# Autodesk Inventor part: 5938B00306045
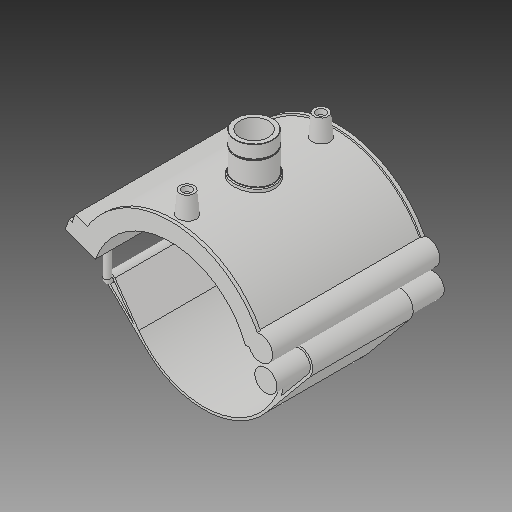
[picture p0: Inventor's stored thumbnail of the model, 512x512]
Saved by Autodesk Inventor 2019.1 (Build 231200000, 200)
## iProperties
Created: 2017-07
Part Number: 5938B00306045
Material: Generic
Description: PLASSON TRANSITION SADDLE 6''IPS x 1"NPT
Document SubType Name: Modeling
Designer: KIM
Density: 1 g/cm^3
Appearance: Default
Author: KIM
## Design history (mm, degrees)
derived "5938B.ipt"
feature "Solid1::5938B.ipt"
tag "TaggingFeature1"
body "Solid1"
other parameters: "d_" = 168, "B_" = 173.736, "H_" = 41.91, "L_" = 176.022, "d_t" = 6, "G_" = 30.291, "d148" = 2.52, "d160" = 2.52, "d169" = 2.52, "d192" = 6.72, "d0" = 168, "d1" = 201.6, "d2" = 434.34, "d3" = 42, "d4" = 176.022, "d5" = 0, "d40" = 104.832, "d41" = 42.4074, "d43" = 0, "d45" = 0, "d47" = 142.71, "d48" = 39.3783, "d50" = 0, "d78" = 122.8, "d79" = 15, "d80" = 70.4088, "d82" = 5 deg, "d84" = 4, "d85" = 14, "d86" = 0, "d87" = 3, "d88" = 0, "d96" = 205.632, "d97" = 3.52044, "d98" = 0, "d102" = 0.90873, "d103" = 30.291, "d104" = 25.146, "d105" = 0, "d106" = 24.2328, "d108" = 0, "d109" = -13.97, "d111" = 0.5, "d112" = 0.5, "d113" = 0, "d114" = 0.5, "d117" = 0.30291, "d120" = 140 deg, "d121" = 24.228, "d122" = 20 deg, "d123" = 806.4, "d124" = 120.96, "d126" = 0, "d143" = 173.04, "d145" = 25.84615, "d149" = 2.52, "d150" = 28.43077, "d153" = 176.022, "d154" = 0, "d156" = 100.8, "d157" = 160 deg, "d159" = 6.72, "d161" = 2.52, "d162" = 105.6132, "d163" = 0, "d164" = 84, "d167" = 16.8, "d168" = 98.34146, "d170" = 2.52, "d172" = 0, "d173" = 1, "d175" = 84, "d176" = 20 deg, "d177" = 11.76, "d178" = 33.6, "d180" = 0, "d183" = 13.44, "d184" = 9.408, "d185" = 57.20715, "d186" = 57.20715, "d187" = 100.8, "d188" = 10.08, "d189" = 11.76, "d190" = 0, "d191" = 120.96, "d193" = 6.72, "d194" = 3.444, "d195" = 90 deg, "d197" = 0, "d199" = 0
